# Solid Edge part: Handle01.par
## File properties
Author: ptcarter
Template: Normal.par
Last saved by: User
Revision: 52
Application: Solid Edge
Accuracy: 0.99
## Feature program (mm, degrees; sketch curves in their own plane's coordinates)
sketch for "unnamed RevolvedProtrusion 1" plane through (0, 0, 0) normal (0, -1, 0) x-axis (1, 0, 0)
  line (-18, 12) -> (-18, 5)
  line (-18, 5) -> (0, 5)
  line (0, 5) -> (0, 0)
  line (0, 0) -> (-23, 0)
  arc centre (-15, 6) radius 10 from (-23, 12) to (-23, 0) ccw
  line (-18, 12) -> (-23, 12)
revolve "unnamed RevolvedProtrusion 1" add about sketch line (0, 10) -> (0, 35)
sketch for "unnamed Protrusion 1" plane through (110, 0, 0) normal (1, 0, 0) x-axis (0, 1, 0)
  line (-12, 9.5) -> (12, 9.5)
  line (12, 9.5) -> (12, 2.5)
  line (12, 2.5) -> (-12, 2.5)
  line (-12, 2.5) -> (-12, 9.5)
extrude "unnamed Protrusion 1" add
sketch for "unnamed Cutout 1" plane through (0, 0, 0) normal (0, 0, 1) x-axis (1, 0, 0)
  arc centre (0, 0) radius 7.5 from (-6, 4.5) to (-6, -4.5) ccw
  line (6, -4.5) -> (-6, -4.5)
  arc centre (0, 0) radius 7.5 from (6, -4.5) to (6, 4.5) ccw
  line (6, 4.5) -> (-6, 4.5)
extrude "unnamed Cutout 1" cut
fillet "Round_8" radius 12
fillet "Round_9" radius 3
fillet "Round_10" radius 3
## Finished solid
Body 1: solid body, 28 faces, 58 edges, 32 vertices.
  Faces by surface: plane 9, cylinder 8, blend 6, torus 5
  Edges by curve: circle 28, line 18, intersection 12
Bounding box of the edges (mm; curved faces can reach further): 133.000 x 46.000 x 12.000, from (-23, -23, 0) to (110, 23, 12).
Cylindrical faces by radius (mm): R3 x4, R7.5 x2, R12 x1, R18 x1
Toroidal faces (ring radius, tube radius in mm): R9 r3 x2, R15 r10 x1, R26.2583 r3 x2
Planar faces by outward normal: +y 2, +z 3, -y 2, -z 2
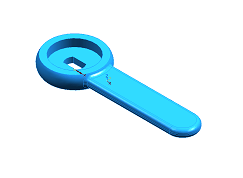
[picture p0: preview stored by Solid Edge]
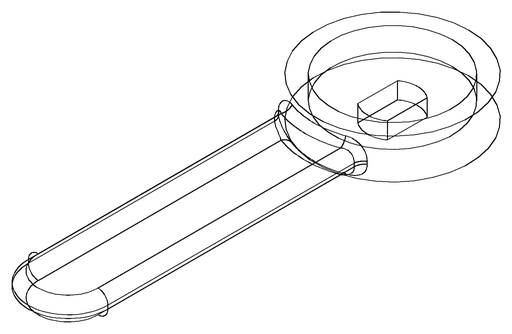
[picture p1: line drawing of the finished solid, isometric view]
